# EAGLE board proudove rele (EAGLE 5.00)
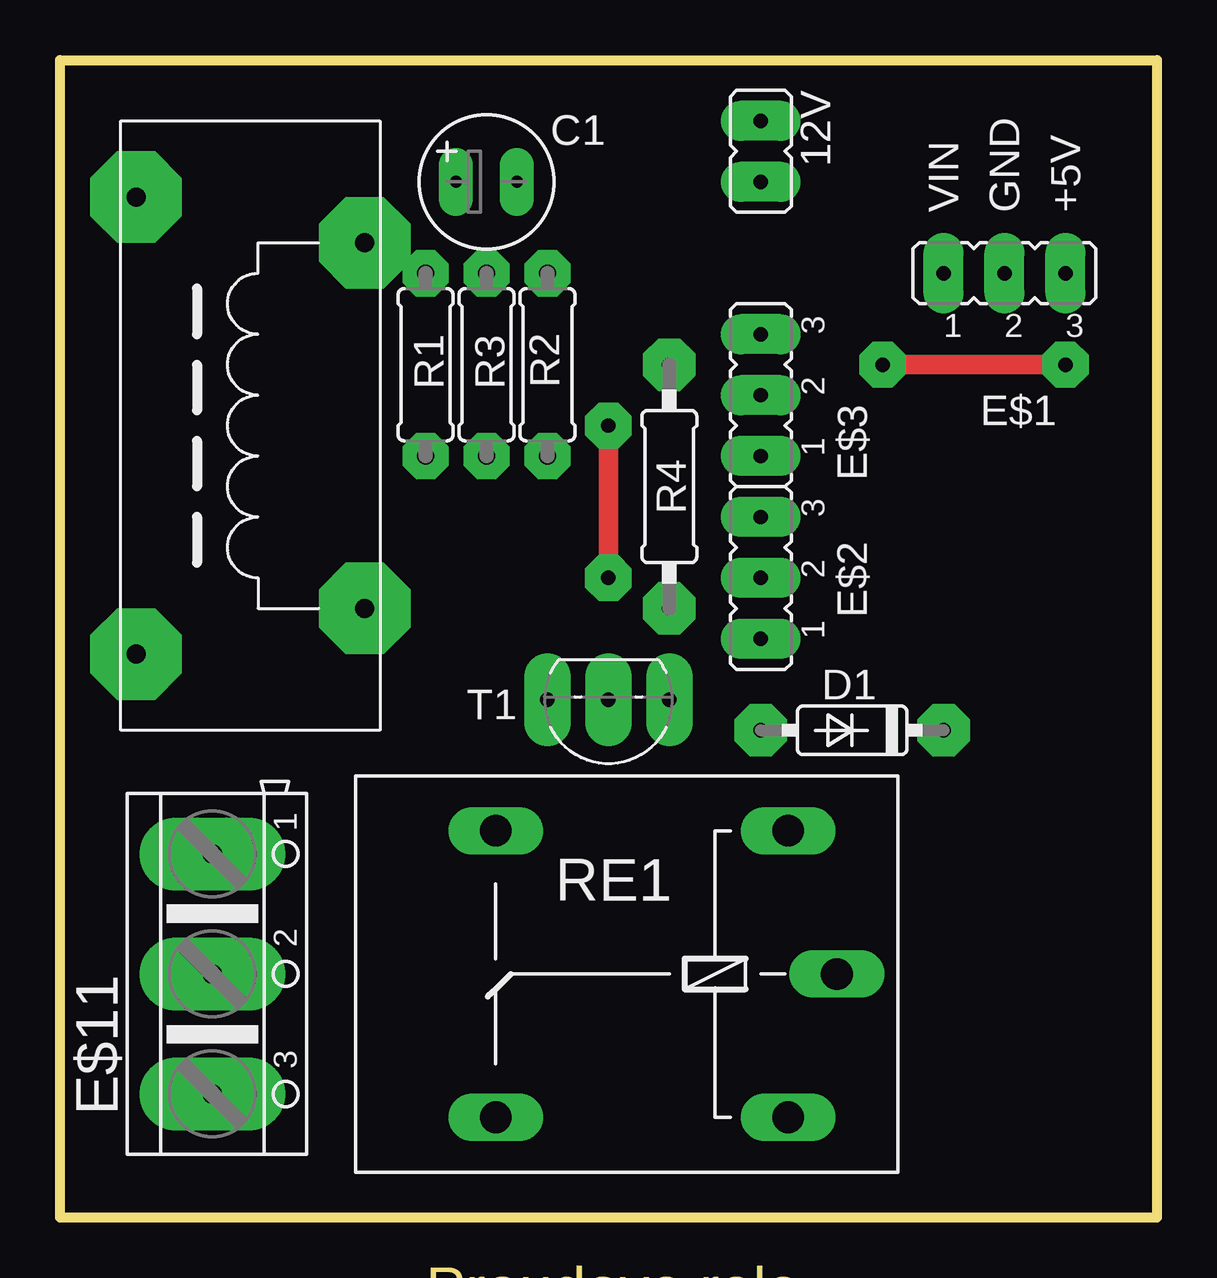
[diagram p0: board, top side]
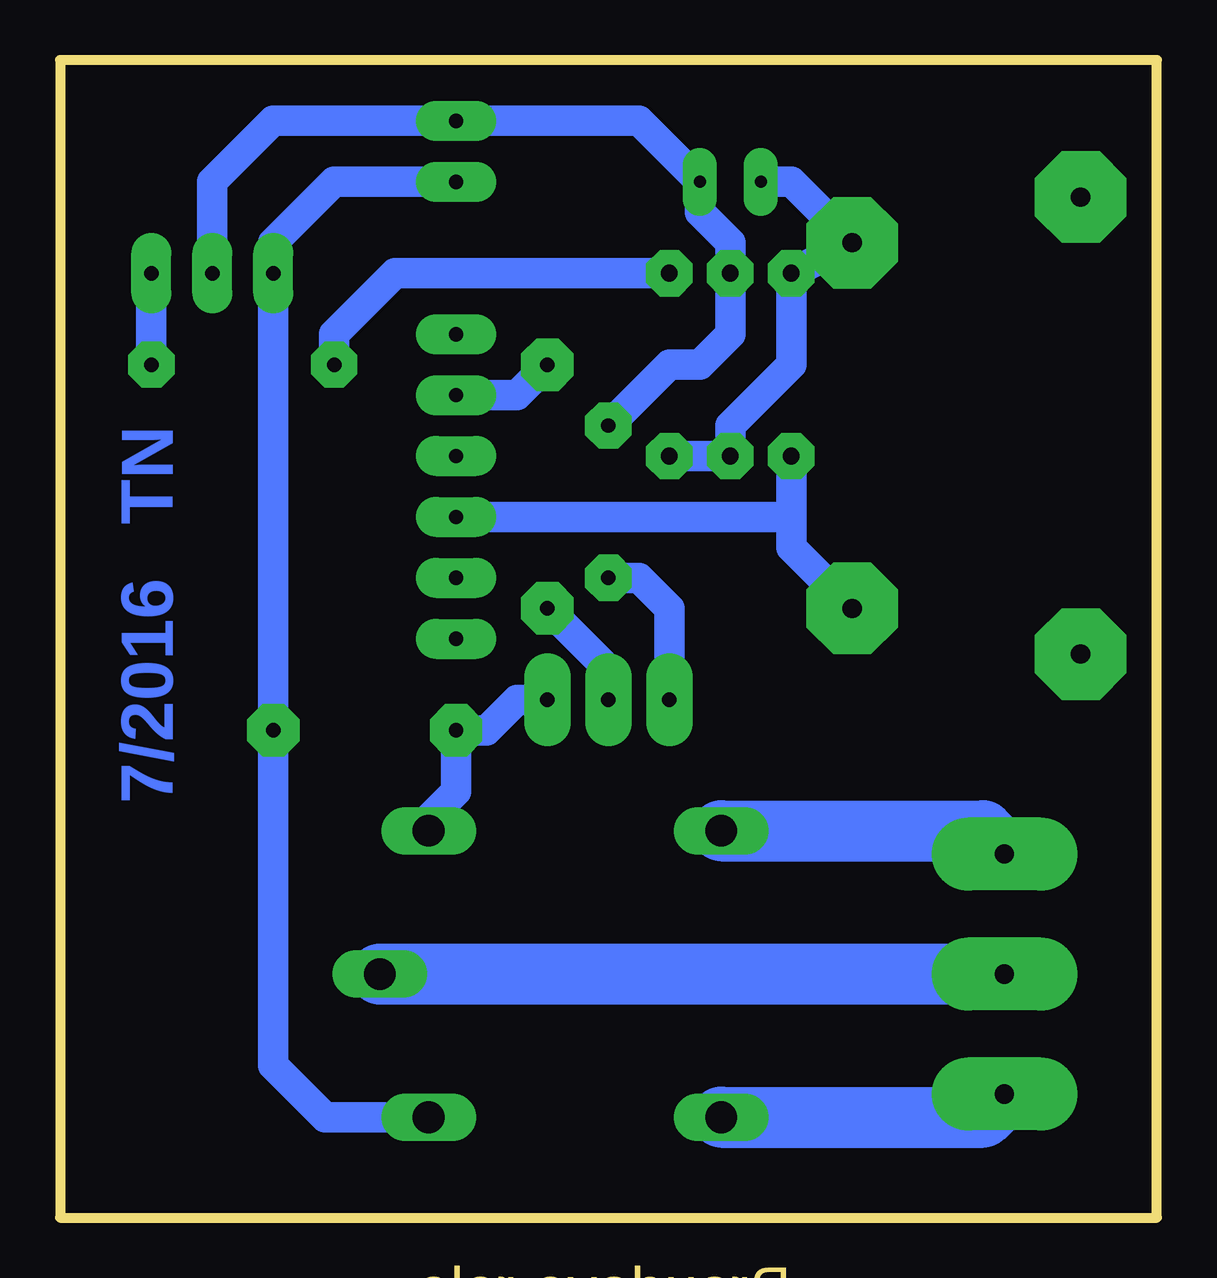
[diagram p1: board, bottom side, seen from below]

Size 45.72 x 48.26 mm. Coordinates in mm from the lower left corner, seen from the top.
Outline: 0,48.26 45.72,48.26 45.72,0 0,0 0,48.26
Copper layers (1*16): Top 0.035mm / dielectric 1.5mm / Bottom 0.035mm
Design rules "default": minimum track width 10mil, minimum drill 24mil, track to track 8mil, track to pad 8mil, pad to pad 8mil, via to via 8mil, smd to smd 8mil, copper to edge 40mil, drill to drill 8mil, minimum pad ring 10mil, minimum via ring 8mil, stop-mask expansion 4mil, vias tented up to drill 0mil, thermal gap 10mil

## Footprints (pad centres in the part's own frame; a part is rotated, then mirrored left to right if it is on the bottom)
JP1 = drill 0.6 pad 1.676 long: 1 0,-1.27; 2 0,1.27
E2,5-6 = drill 0.5 pad 1.422 long: + -1.27,0; - 1.27,0
DO35-7 = drill 0.6 pad 2.184 octagon: A 3.81,0; C -3.81,0
JP2Y = drill 0.6 pad 1.676 long: 1 -2.54,0; 2 0,0; 3 2.54,0
AK500/3 = drill 0.8 pad 3.048 long: 1 -5.004,0; 2 0,0; 3 5.004,0
PROUDOVE_TRAFO = drill 0.8 pad 3.81 octagon: P$1 0,0; P$2 15.24,0; P$3 -1.905,9.525; P$4 17.145,9.525
0207/7 = drill 0.7 pad 1.93 octagon: 1 -3.81,0; 2 3.81,0
0207/10 = drill 0.6 pad 2.184 octagon: 1 -5.08,0; 2 5.08,0
G5LE = drill 1.321 long: 1 -7.493,-5.969; 2 -7.493,5.969; O 4.699,5.969; P -9.525,0; S 4.699,-5.969
TO92-CBE = drill 0.6 pad 1.93 long: B 0,0; C -2.54,0; E 2.54,0

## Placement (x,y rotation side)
12V  [JP1]  29.21,44.45 180 top
C1  [E2,5-6]  17.78,43.18 0 top
D1  [DO35-7]  33.02,20.32 180 top
E$1  [JP2Y]  39.37,39.37 0 top
E$2  [JP2Y]  29.21,26.67 90 top
E$3  [JP2Y]  29.21,34.29 90 top
E$11  [AK500/3]  6.35,10.16 270 top
E$14  [PROUDOVE_TRAFO]  12.7,25.4 90 top
R1  [0207/7]  15.24,35.56 270 top
R2  [0207/7]  20.32,35.56 90 top
R3  [0207/7]  17.78,35.56 270 top
R4  [0207/10]  25.4,30.48 90 top
RE1  [G5LE]  22.86,10.16 180 top
T1  [TO92-CBE]  22.86,21.59 180 top

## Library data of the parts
12V C1 D1 E$1-E$3 E$11 E$14 R1-R4 T1 = 11moje
RE1 = relay

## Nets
5V: E$1.3 R2.2
GND: 12V.1 C1.- E$1.2 R3.1 T1.E
S$1: D1.A RE1.1 T1.C
S$2: R4.1 T1.B
S$3: E$2.3 E$14.P$1 R1.2
S$4: E$3.2 R4.2
S$5: E$11.3 RE1.O
S$6: C1.+ E$14.P$2 R1.1 R2.1 R3.2
S$7: E$11.2 RE1.P
S$8: E$11.1 RE1.S
VIN: 12V.2 D1.C E$1.1 RE1.2

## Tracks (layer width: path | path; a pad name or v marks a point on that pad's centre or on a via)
5V  (via drill 0.6 pad 1.93)
  Top 0.813: v34.29,35.56 v41.91,35.56
  Bottom 1.27: R2.2 31.75,39.37 34.29,36.83 v34.29,35.56 | v41.91,35.56 E$1.3
GND  (via drill 0.6 pad 1.93)
  Top 0.813: v22.86,26.67 v22.86,33.02
  Bottom 1.27: E$1.2 39.37,43.18 36.83,45.72 12V.1 21.59,45.72 C1.- 19.05,41.91 17.78,40.64 R3.1 17.78,36.83 19.05,35.56 20.32,35.56 v22.86,33.02 | v22.86,26.67 21.59,26.67 20.32,25.4 T1.E
S$1
  Bottom 1.27: T1.C 26.67,21.59 27.94,20.32 D1.A 29.21,17.78 30.48,16.51 30.35,16.38 RE1.1
S$2
  Bottom 1.27: T1.B 22.86,22.86 R4.1
S$3
  Bottom 1.27: 15.24,29.21 15.24,27.94 E$14.P$1 | 15.24,29.21 R1.2 | 15.24,29.21 E$2.3
S$4
  Bottom 1.27: E$3.2 26.67,34.29 R4.2
S$5
  Bottom 2.54: E$11.3 6.35,5.08 7.24,4.19 RE1.O
S$6
  Bottom 1.27: C1.+ 15.24,43.18 E$14.P$2 R1.1 15.24,35.56 17.78,33.02 R3.2 R2.1
S$7
  Bottom 2.54: RE1.P E$11.2
S$8
  Bottom 2.54: E$11.1 6.35,15.24 7.24,16.13 RE1.S
VIN
  Bottom 1.27: 12V.2 34.29,43.18 36.83,40.64 E$1.1 D1.C 36.83,6.35 34.67,4.19 RE1.2

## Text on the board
Bottom: TN | 7/2016
Dimension: Proudove rele
tNames: VIN | GND | +5V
